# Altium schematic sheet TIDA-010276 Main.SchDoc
size 431 x 279 mm; Date: Not shown in title block; ApprovedBy: Not shown in title block; CheckedBy: Not shown in title block; Author: Not shown in title block; CompanyName: Not shown in title block; DrawnBy: Jenson Fang; Engineer: Jenson Fang; Organization: Not shown in title block; Address1: Not shown in title block; Address2: Not shown in title block; Address3: Not shown in title block; Address4: Not shown in title block; DocumentNumber: 1; Revision: Use project parameter SCH_Rev; SheetNumber: 1; SheetTotal: 6; PageSetup: Record=PageOptions¦CenterHorizontal=True¦CenterVertical=True¦PrintScale=1.00¦XCorrection=1.00¦YCorrection=1.00¦PrintKind=0¦BorderSize=5000000¦LeftOffset=0¦BottomOffset=0¦Orientation=2¦PaperLength=1000¦PaperWidth=1000¦Scale=100¦PaperSource=15¦PrintQuality=600¦MediaType=1¦DitherType=10¦PaperKind=Letter¦PrintScaleMode=1
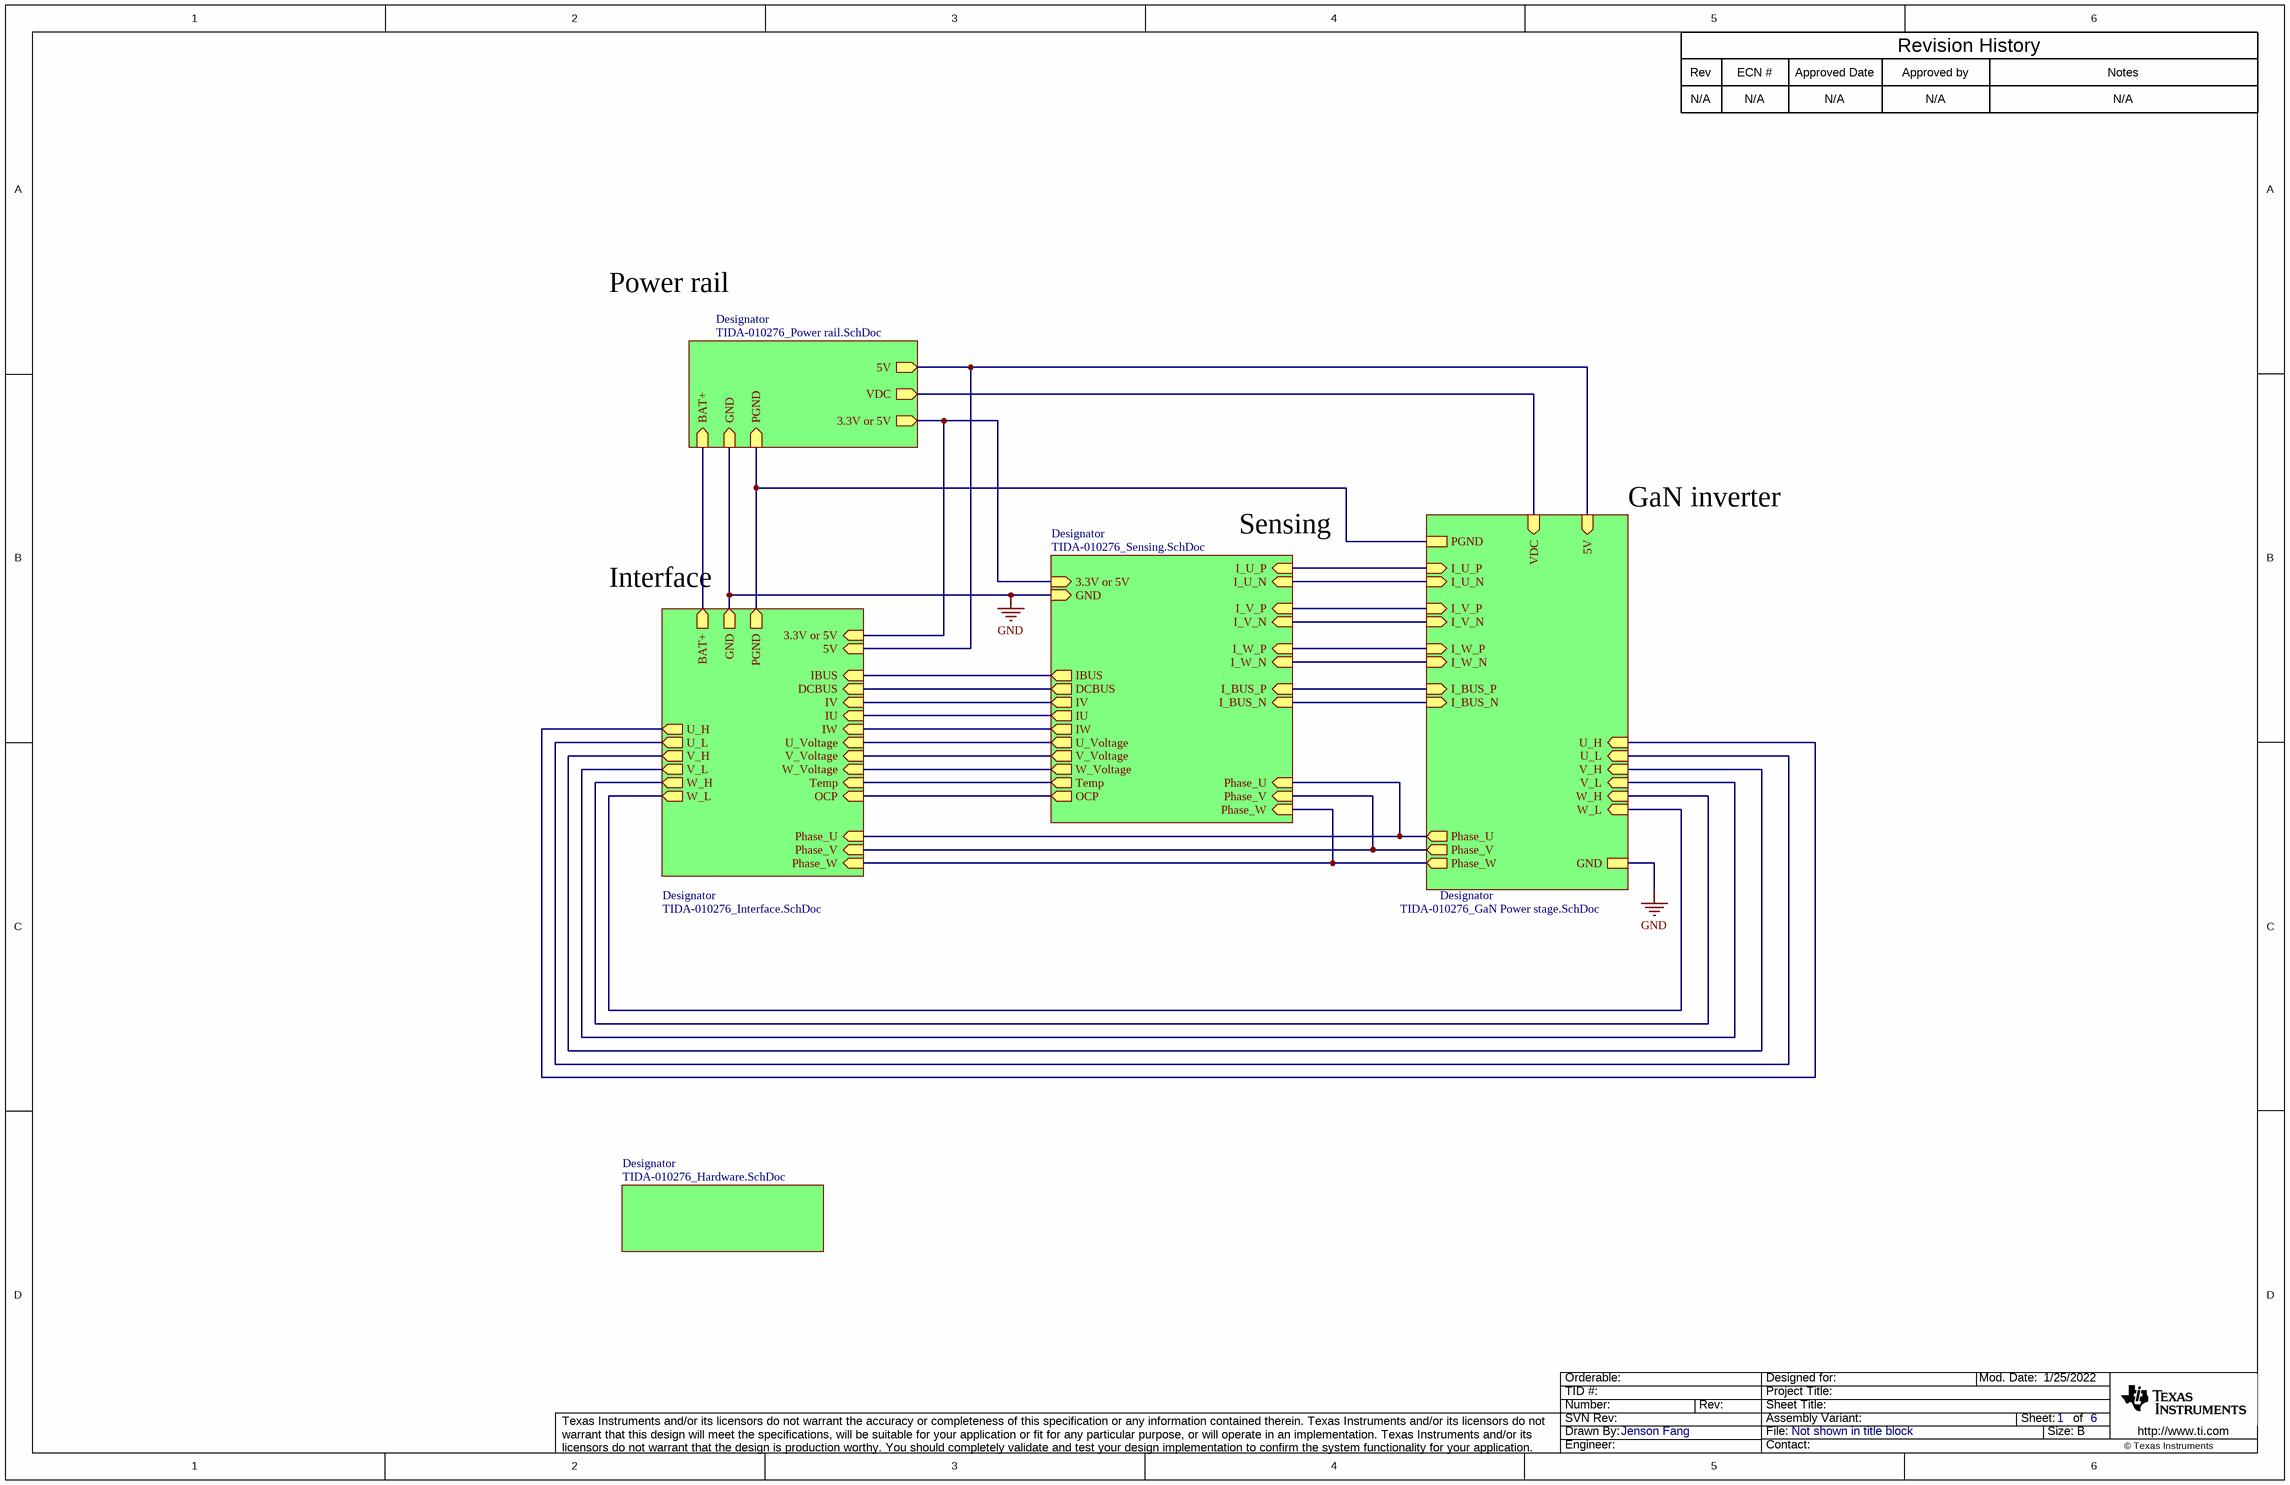
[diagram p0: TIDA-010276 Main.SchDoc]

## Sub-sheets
Designator = TIDA-010276_GaN Power stage.SchDoc: Phase_U (out), Phase_V (out), Phase_W (out), I_U_P (in), I_U_N (in), I_V_N (in), I_V_P (in), I_W_N (in), I_BUS_P (in), I_BUS_N (in), U_H (in), U_L (in), V_H (in), V_L (in), W_H (in), W_L (in), 5V (in), I_W_P (in), VDC (in), PGND, GND
Designator = TIDA-010276_Sensing.SchDoc: I_BUS_P (in), I_BUS_N (in), I_V_N (in), I_V_P (in), I_W_P (in), IV (out), IU (out), IW (out), DCBUS (out), Temp (out), Phase_U (in), Phase_V (in), Phase_W (in), U_Voltage (out), V_Voltage (out), W_Voltage (out), IBUS (out), I_U_P (in), I_U_N (in), I_W_N (in), OCP (out), 3.3V or 5V (in), GND (in)
Designator = TIDA-010276_Power rail.SchDoc: BAT+ (in), GND (in), VDC (out), 5V (out), 3.3V or 5V (out), PGND (in)
Designator = TIDA-010276_Interface.SchDoc: U_H (out), U_L (out), V_H (out), V_L (out), W_L (out), W_H (out), DCBUS (in), U_Voltage (in), V_Voltage (in), W_Voltage (in), IBUS (in), IU (in), IV (in), IW (in), BAT+ (out), GND (out), Phase_U (in), Phase_V (in), Phase_W (in), Temp (in), OCP (in), 3.3V or 5V (in), 5V (in), PGND (out)
Designator = TIDA-010276_Hardware.SchDoc: no entries

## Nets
GND: sheet Designator/GND, sheet Designator/GND, sheet Designator/GND, sheet Designator/GND
(unnamed): sheet Designator/Phase_U, sheet Designator/Phase_U, sheet Designator/Phase_U
(unnamed): sheet Designator/Phase_V, sheet Designator/Phase_V, sheet Designator/Phase_V  [a separate net that carries the same name]
(unnamed): sheet Designator/Phase_W, sheet Designator/Phase_W, sheet Designator/Phase_W  [a separate net that carries the same name]
(unnamed): sheet Designator/I_U_P, sheet Designator/I_U_P  [a separate net that carries the same name]
(unnamed): sheet Designator/I_U_N, sheet Designator/I_U_N  [a separate net that carries the same name]
(unnamed): sheet Designator/I_V_N, sheet Designator/I_V_N  [a separate net that carries the same name]
(unnamed): sheet Designator/I_V_P, sheet Designator/I_V_P  [a separate net that carries the same name]
(unnamed): sheet Designator/I_W_N, sheet Designator/I_W_N  [a separate net that carries the same name]
(unnamed): sheet Designator/I_BUS_P, sheet Designator/I_BUS_P  [a separate net that carries the same name]
(unnamed): sheet Designator/I_BUS_N, sheet Designator/I_BUS_N  [a separate net that carries the same name]
(unnamed): sheet Designator/U_H, sheet Designator/U_H  [a separate net that carries the same name]
(unnamed): sheet Designator/U_L, sheet Designator/U_L  [a separate net that carries the same name]
(unnamed): sheet Designator/V_H, sheet Designator/V_H  [a separate net that carries the same name]
(unnamed): sheet Designator/V_L, sheet Designator/V_L  [a separate net that carries the same name]
(unnamed): sheet Designator/W_H, sheet Designator/W_H  [a separate net that carries the same name]
(unnamed): sheet Designator/W_L, sheet Designator/W_L  [a separate net that carries the same name]
(unnamed): sheet Designator/5V, sheet Designator/5V, sheet Designator/5V  [a separate net that carries the same name]
(unnamed): sheet Designator/I_W_P, sheet Designator/I_W_P  [a separate net that carries the same name]
(unnamed): sheet Designator/VDC, sheet Designator/VDC  [a separate net that carries the same name]
(unnamed): sheet Designator/PGND, sheet Designator/PGND, sheet Designator/PGND  [a separate net that carries the same name]
(unnamed): sheet Designator/IV, sheet Designator/IV  [a separate net that carries the same name]
(unnamed): sheet Designator/IU, sheet Designator/IU  [a separate net that carries the same name]
(unnamed): sheet Designator/IW, sheet Designator/IW  [a separate net that carries the same name]
(unnamed): sheet Designator/DCBUS, sheet Designator/DCBUS  [a separate net that carries the same name]
(unnamed): sheet Designator/Temp, sheet Designator/Temp  [a separate net that carries the same name]
(unnamed): sheet Designator/U_Voltage, sheet Designator/U_Voltage  [a separate net that carries the same name]
(unnamed): sheet Designator/V_Voltage, sheet Designator/V_Voltage  [a separate net that carries the same name]
(unnamed): sheet Designator/W_Voltage, sheet Designator/W_Voltage  [a separate net that carries the same name]
(unnamed): sheet Designator/IBUS, sheet Designator/IBUS  [a separate net that carries the same name]
(unnamed): sheet Designator/OCP, sheet Designator/OCP  [a separate net that carries the same name]
(unnamed): sheet Designator/3.3V or 5V, sheet Designator/3.3V or 5V, sheet Designator/3.3V or 5V  [a separate net that carries the same name]
(unnamed): sheet Designator/BAT+, sheet Designator/BAT+  [a separate net that carries the same name]

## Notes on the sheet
- Rev
- N/A
- ECN #
- Approved Date
- Approved by
- Revision History
- Notes
- Power rail
- Sensing
- GaN inverter
- Interface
